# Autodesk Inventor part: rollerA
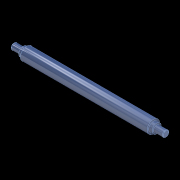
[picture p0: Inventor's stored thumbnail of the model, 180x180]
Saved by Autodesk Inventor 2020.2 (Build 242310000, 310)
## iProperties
Manager: PART
Category: 14
Company: 13
Created: 2020-10
Part Number: rollerA
Material: Generic
Document SubType Name: Modeling
Designer: Apardo
Density: 1 g/cm^3
Appearance: Flaked Satin - Blue
Project: PLATE ROLLING MACHINE
Cost Center: 1
Description: ROLLER A
Engineer: STEEL C45
Vendor: 14
Stock Number: 1.9
Engr Approved By: D. JAEGER
Author: Apardo
Revision Number: 1.0
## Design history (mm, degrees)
sketch "Sketch1"
  geometry: L1 (0, 0)-(-263.363, 0); L2 (-180, 0)-(-180, 7.5); L3 (-180, 7.5)-(-158, 7.5); L4 (-158, 7.5)-(-158, 11); L5 (-158, 11)-(-150, 11); L6 (-150, 11)-(-150, 15); L7 (-150, 15)-(150, 15); L8 (150, 15)-(150, 11); L9 (150, 11)-(158, 11); L10 (158, 11)-(158, 7.5); L11 (158, 7.5)-(180, 7.5); L12 (180, 7.5)-(180, 0); L13 (180, 0)-(-180, 0); 1 further point
  constraints: 26 end point, 10 perpendicular, 4 collinear, 2 vertical, 1 horizontal, 1 point on line
  dimensions: "d0" = 360 distance of L12.end L2.start; "d1" = 180 distance from line of L1.start L2 (= 0.5 x d0); "d2" = 30 diameter of L7 L1; "d3" = 15 diameter of L11 L1; "d4" = 22 diameter of L9 L1; "d5" = 22 distance of L10.end L11.end; "d6" = 30 distance from line of L8 L12.end
revolve "Revolution1" sketch "Sketch1" stored, may be unused: angle "d7" = 90 deg
chamfer "Chamfer1" distance "d8" = 1; stored, may be unused: second distance "d9" = 2, angle "d10" = 45 deg
body "Solid1"
